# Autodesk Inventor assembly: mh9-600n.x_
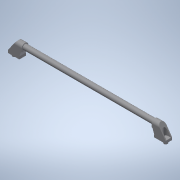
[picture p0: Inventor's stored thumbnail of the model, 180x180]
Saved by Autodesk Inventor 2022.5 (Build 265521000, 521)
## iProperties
Part Number: mh9-600n.x_
Material: 一般
Document SubType Name: Assembly
Designer: ImaoCorp
Sending System: SOLIDWORKS 2017-2017317
MC: AMD64
MC_MODEL: Intel64 Family 6 Model 60 Stepping 3, GenuineIntel
OS: Windows_NT
FRU: Parasolid Version 29.0, build 201,  4-17-2017
FORMAT: text
GUISE: transmit
KEY: mh9-600n
FILE: mh9-600n.x_t
DATE: Fri Jul 26 11:47:57 2019
Author: ImaoCorp
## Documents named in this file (4)
- X:\14_SW2022-Inv2022\00_全2023-1023新製品(TCC)まで\m\mh9-600n\MH9-600N.iam
- X:\14_SW2022-Inv2022\00_全2023-1023新製品(TCC)まで\m\mh9-600n\mh9-600n_01.ipt
- X:\14_SW2022-Inv2022\00_全2023-1023新製品(TCC)まで\m\mh9-600n\mh9-600n_02.ipt
- X:\14_SW2022-Inv2022\00_全2023-1023新製品(TCC)まで\m\mh9-600n\mh9-600n_03.ipt
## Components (3 placed, 3 different names)
1. mh9-600n_01
2. mh9-600n_02
3. mh9-600n_03
